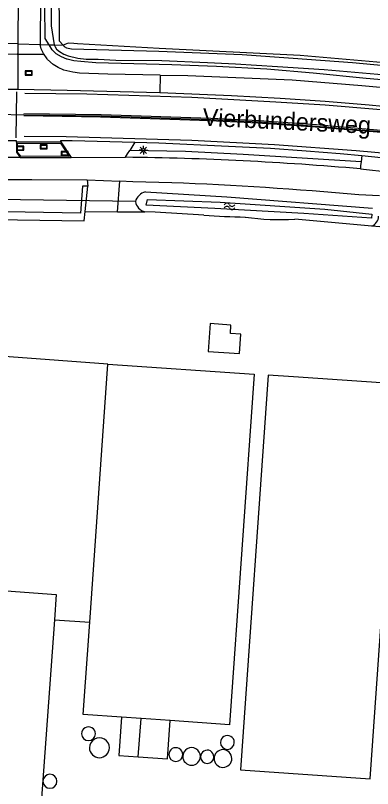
# Model space of a CAD drawing. Extents: x 124000 to 128010, y 398999 to 403000.
# Drawn here: x 125582.7 to 125633.9, y 402700.9 to 402811.8 of the extents above; entities that cross this region are included whole.
import ezdxf

# ---------------------------------------------------------------- set-up
doc = ezdxf.new("R2010")
doc.units = 0
for name, color, linetype in [('gg-afsc-lijn draadraster', 7, 'Continuous'), ('gg-afsc-muur', 7, 'Continuous'), ('gg-anno-openbare ruimte label', 7, 'Continuous'), ('gg-bbg-bijgebouw', 7, 'Continuous'), ('gg-bbg-gedigitaliseerde bijgebouw', 7, 'Continuous'), ('gg-bbg-luifel en loopbrug', 7, 'Continuous'), ('gg-bbg-opslagtank', 7, 'Continuous'), ('gg-bbg-tussenscheiding', 7, 'Continuous'), ('gg-knt-bronhoudergrens', 7, 'Continuous'), ('gg-knt-verharding', 7, 'Continuous'), ('gg-kntw-beschoeiing', 7, 'Continuous'), ('gg-kntw-bovenkant insteek waterloop', 7, 'Continuous'), ('gg-kntw-waterlijn', 7, 'Continuous'), ('gg-kwrk-duiker nz buis', 7, 'Continuous'), ('gt-grn-groengrens', 7, 'Continuous'), ('gt-grn-vlakafsluiter', 7, 'Continuous'), ('gt-grn-weggrens', 7, 'Continuous'), ('gt-symb-bord', 7, 'Continuous'), ('gt-symb-lichtmast', 7, 'Continuous'), ('gt-symb-straatnaambord', 7, 'Continuous'), ('gt-symb-verkeersbord', 7, 'Continuous'), ('gt-symb-watersymbool', 7, 'Continuous'), ('gx-grn-maaiveld', 7, 'Continuous'), ('gx-knt-lijn weginrichtingselement', 7, 'Continuous')]:
    doc.layers.add(name, color=color, linetype=linetype)

# ---------------------------------------------------------------- blocks, each defined once
blk = doc.blocks.new('gt0-BORD')
at = {"layer": 'gt-symb-bord'}
blk.add_lwpolyline([(-0.5, 0.29), (-0.5, -0.29), (0.5, -0.29), (0.5, 0.29), (-0.5, 0.29)], dxfattribs=at)
blk.add_lwpolyline([(-0.42, -0.21), (0.42, -0.21), (0.42, 0.21), (-0.42, 0.21)], close=True, dxfattribs=at)
blk = doc.blocks.new('gt0-LMAST')
at = {"layer": 'gt-symb-lichtmast'}
for p, q in [((-0.18, 0.17), (-0.45, 0.44)), ((-0.01, 0.25), (-0.01, 0.62)), ((0.17, 0.17), (0.44, 0.44)), ((-0.26, 0), (-0.63, 0)), ((-0.18, -0.18), (-0.45, -0.45)), ((-0.01, -0.25), (-0.01, -0.63)), ((0.44, -0.45), (0.17, -0.18)), ((0.24, 0), (0.62, 0))]:
    blk.add_line(p, q, dxfattribs=at)
blk.add_circle((-0.01, 0), 0.25, dxfattribs=at)
blk = doc.blocks.new('gt0-SBORD')
at = {"layer": 'gt-symb-straatnaambord'}
blk.add_lwpolyline([(-0.5, 0.29), (-0.5, -0.29), (0.5, -0.29), (0.5, 0.29), (-0.5, 0.29)], dxfattribs=at)
blk.add_lwpolyline([(-0.42, -0.21), (0.42, -0.21), (0.42, 0.21), (-0.42, 0.21)], close=True, dxfattribs=at)
blk = doc.blocks.new('gt0-VBORD')
at = {"layer": 'gt-symb-verkeersbord'}
blk.add_lwpolyline([(-0.5, 0.29), (-0.5, -0.29), (0.5, -0.29), (0.5, 0.29), (-0.5, 0.29)], dxfattribs=at)
blk.add_lwpolyline([(-0.42, -0.21), (0.42, -0.21), (0.42, 0.21), (-0.42, 0.21)], close=True, dxfattribs=at)
blk = doc.blocks.new('gt0-WA')
at = {"layer": 'gt-symb-watersymbool'}
for centre, start, end in [((-0.32, 0.02), 28.0725, 151.9275), ((0.43, 0.42), 208.0725, 331.9275), ((-0.32, -0.43), 28.0725, 151.9275), ((0.43, -0.03), 208.0725, 331.9275)]:
    blk.add_arc(centre, 0.425, start, end, dxfattribs=at)

msp = doc.modelspace()

# ---------------------------------------------------------------- linework, layer by layer
at = {"layer": 'gg-afsc-lijn draadraster'}
msp.add_lwpolyline([(125692.77, 402796.89), (125673.2, 402800.96), (125670.49, 402801.3), (125660.84, 402802.3), (125646.47, 402803.91), (125635.61, 402805.02), (125623.48, 402806.08), (125603.27, 402807.11), (125591.59, 402807.78), (125591.02, 402807.81), (125590.22, 402807.85)], dxfattribs=at)
at = {"layer": 'gg-afsc-muur'}
msp.add_line((125582.9, 402806.26), (125579.49, 402806.24), dxfattribs=at)
at = {"layer": 'gg-bbg-bijgebouw'}
for p, q in [((125637.43, 402758.95), (125622.53, 402759.98)), ((125600.68, 402710.95), (125597.89, 402711.15)), ((125604.87, 402710.66), (125600.68, 402710.95))]:
    msp.add_line(p, q, dxfattribs=at)
for points in [[(125595.94, 402761.81), (125574.66, 402763.37), (125574.59, 402762.34)], [(125595.94, 402761.81), (125616.89, 402760.36), (125613.35, 402710.06), (125604.87, 402710.66)], [(125622.53, 402759.98), (125618.91, 402760.23), (125614.93, 402703.59)], [(125614.93, 402703.59), (125633.54, 402702.28), (125637.52, 402758.94)], [(125597.89, 402711.15), (125592.4, 402711.54), (125593.33, 402724.76)]]:
    msp.add_lwpolyline(points, dxfattribs=at)
at = {"layer": 'gg-bbg-gedigitaliseerde bijgebouw'}
msp.add_line((125588.27, 402725.13), (125593.33, 402724.76), dxfattribs=at)
msp.add_lwpolyline([(125588.27, 402725.13), (125585.66, 402689), (125581.03, 402689.34)], dxfattribs=at)
at = {"layer": 'gg-bbg-luifel en loopbrug'}
msp.add_line((125600.28, 402705.45), (125600.68, 402710.95), dxfattribs=at)
for points in [[(125610.58, 402767.62), (125610.29, 402763.63), (125614.78, 402763.31), (125614.98, 402766.1), (125613.49, 402766.21), (125613.57, 402767.41), (125610.58, 402767.62)], [(125597.89, 402711.15), (125597.49, 402705.65), (125600.28, 402705.45)], [(125600.28, 402705.45), (125604.47, 402705.15), (125604.87, 402710.66)]]:
    msp.add_lwpolyline(points, dxfattribs=at)
at = {"layer": 'gg-bbg-opslagtank'}
for centre, radius, start, end in [((125593.15, 402708.77), 0.988, 0.0579, 180.116), ((125593.15, 402708.77), 0.988, 180.1159, 0.058), ((125594.71, 402706.76), 1.43, 359.9799, 180.0201), ((125613.06, 402707.52), 0.996, 0.0575, 180.1151), ((125613.06, 402707.52), 0.996, 180.115, 0.0576), ((125594.71, 402706.76), 1.43, 180.0201, 359.9799), ((125605.66, 402705.77), 0.993, 0.0577, 180.1154), ((125607.93, 402705.51), 1.26, 0.0227, 180.0681), ((125610.17, 402705.46), 0.955, 0.0599, 180.12), ((125612.43, 402705.21), 1.27, 0.0903, 180.0451), ((125605.66, 402705.77), 0.993, 180.1154, 0.0577), ((125607.93, 402705.51), 1.26, 180.0681, 0.0227), ((125610.17, 402705.46), 0.955, 180.1199, 0.06), ((125612.43, 402705.21), 1.27, 180.0903, 0.0451), ((125587.62, 402701.94), 1, 0.0856, 180.0856), ((125587.62, 402701.94), 1, 180.0856, 0.0856)]:
    msp.add_arc(centre, radius, start, end, dxfattribs=at)
at = {"layer": 'gg-bbg-tussenscheiding'}
msp.add_line((125593.33, 402724.76), (125595.94, 402761.81), dxfattribs=at)
msp.add_lwpolyline([(125571.65, 402729.97), (125588.53, 402728.75), (125588.27, 402725.13)], dxfattribs=at)
at = {"layer": 'gg-knt-bronhoudergrens'}
for p, q in [((125632.13, 402789.82), (125644.24, 402788.57)), ((125592.96, 402788.24), (125593.07, 402787.35)), ((125592.67, 402783.7), (125593.07, 402787.35))]:
    msp.add_line(p, q, dxfattribs=at)
for points in [[(125593.07, 402787.35), (125592.29, 402787.35), (125592.01, 402783.47), (125557.56, 402784.07), (125557.81, 402787.89)], [(125594.97, 402672.63), (125550.97, 402693.85), (125553.52, 402725.77), (125557.43, 402782.88), (125592.52, 402782.35), (125592.67, 402783.7)]]:
    msp.add_lwpolyline(points, dxfattribs=at)
at = {"layer": 'gg-knt-verharding'}
msp.add_line((125634.88, 402785.97), (125631.93, 402786.09), dxfattribs=at)
msp.add_lwpolyline([(125605.09, 402787.82), (125599.48, 402787.96), (125597.62, 402788.08)], dxfattribs=at)
for centre, radius, start, end in [((125593.63, 402353.4), 438.11, 84.9589, 89.3681), ((125584.76, 402263.53), 524.69, 84.8429, 87.7796)]:
    msp.add_arc(centre, radius, start, end, dxfattribs=at)
at = {"layer": 'gg-kntw-beschoeiing'}
msp.add_line((125582.9, 402806.26), (125586.7, 402806.27), dxfattribs=at)
at = {"layer": 'gg-kntw-bovenkant insteek waterloop'}
for p, q in [((125602.71, 402783.59), (125601.22, 402783.67)), ((125609.69, 402783.19), (125602.71, 402783.59)), ((125633.76, 402781.59), (125622.73, 402782.59))]:
    msp.add_line(p, q, dxfattribs=at)
msp.add_lwpolyline([(125601.3, 402786.51), (125612.99, 402785.81), (125633.87, 402784.18)], dxfattribs=at)
for centre, radius, start, end in [((125601.67, 402784.69), 1.85, 101.5261, 166.2673), ((125601.61, 402785.39), 1.76, 188.3735, 257.1885), ((125618.54, 402902), 119.14, 265.7375, 268.6002), ((125620.8, 402819.57), 37.03, 261.9878, 272.9917), ((125633.08, 402783.1), 1.67, 294.3526, 357.2073)]:
    msp.add_arc(centre, radius, start, end, dxfattribs=at)
at = {"layer": 'gg-kntw-waterlijn'}
msp.add_lwpolyline([(125601.61, 402785.43), (125612.04, 402785.05), (125627.01, 402784.04), (125633.79, 402783.34), (125633.73, 402782.73), (125624.04, 402783.4), (125611.27, 402784.15), (125601.4, 402784.59), (125601.61, 402785.43)], dxfattribs=at)
at = {"layer": 'gg-kwrk-duiker nz buis'}
msp.add_line((125599.87, 402785.13), (125546.26, 402785.98), dxfattribs=at)
at = {"layer": 'gt-grn-groengrens'}
for p, q in [((125597.29, 402783.64), (125601.22, 402783.67)), ((125635.51, 402781.44), (125633.76, 402781.59))]:
    msp.add_line(p, q, dxfattribs=at)
at = {"layer": 'gt-grn-vlakafsluiter'}
msp.add_line((125597.29, 402783.64), (125597.62, 402788.08), dxfattribs=at)
at = {"layer": 'gt-grn-weggrens'}
msp.add_line((125592.67, 402783.7), (125597.29, 402783.64), dxfattribs=at)
at = {"layer": 'gx-grn-maaiveld'}
for p, q in [((125583.13, 402819.31), (125583, 402807.76)), ((125586.3, 402819.29), (125586.2, 402807.66)), ((125583, 402807.76), (125577.64, 402807.87)), ((125583, 402807.76), (125583.03, 402805.68)), ((125583, 402807.76), (125586.2, 402807.66)), ((125586.2, 402807.66), (125587.51, 402807.63)), ((125587.51, 402807.63), (125588.23, 402807.61)), ((125588.23, 402807.61), (125589.51, 402807.57)), ((125583.03, 402805.68), (125583.01, 402801.27)), ((125603.41, 402803.28), (125603.38, 402800.8)), ((125581.3, 402801.26), (125583.01, 402801.27)), ((125589.19, 402793.68), (125582.81, 402793.67)), ((125589.19, 402793.68), (125590.64, 402791.43)), ((125599.79, 402793.65), (125599.07, 402792.48)), ((125583.37, 402791.47), (125580.84, 402791.46)), ((125583.37, 402791.47), (125590.64, 402791.43)), ((125590.64, 402791.43), (125598.46, 402791.49)), ((125632.35, 402791.75), (125632.22, 402790.82)), ((125632.35, 402791.75), (125644.49, 402790.5)), ((125592.96, 402788.24), (125597.62, 402788.08))]:
    msp.add_line(p, q, dxfattribs=at)
for points in [[(125624.11, 402880.43), (125606.85, 402854.76), (125588.86, 402825.8), (125588.93, 402808.19), (125589.51, 402807.57)], [(125587.84, 402820.39), (125587.79, 402810.33), (125588.23, 402807.61)], [(125587.51, 402807.63), (125586.93, 402808.55), (125586.9, 402813.2)], [(125587.2, 402805.63), (125586.67, 402806.4), (125586.38, 402807.06), (125586.2, 402807.66)], [(125590.03, 402805.58), (125589.26, 402805.89), (125588.53, 402806.35), (125587.95, 402806.92), (125587.51, 402807.63)], [(125588.23, 402807.61), (125588.36, 402807.35), (125588.57, 402807.02), (125589.01, 402806.64), (125589.6, 402806.3), (125590.24, 402806.06), (125591.64, 402805.72), (125592.79, 402805.57), (125594.51, 402805.55), (125597.06, 402805.42), (125603.66, 402805.37), (125610.22, 402805.09), (125614.2, 402804.89), (125620.25, 402804.52), (125626.95, 402804.06), (125635.71, 402803.3), (125643, 402802.53), (125643.44, 402802.45)], [(125692.77, 402796.89), (125673.2, 402800.96), (125670.49, 402801.3), (125660.84, 402802.3), (125646.47, 402803.91), (125635.61, 402805.02), (125623.48, 402806.08), (125603.27, 402807.11), (125591.59, 402807.78), (125591.02, 402807.81), (125590.22, 402807.85), (125589.51, 402807.57)], [(125589.51, 402807.57), (125589.64, 402807.38), (125589.98, 402807.19), (125590.7, 402807.04), (125603.21, 402806.71), (125615.19, 402806.21), (125622.48, 402805.72), (125630.99, 402805.1), (125644.75, 402803.79), (125645.29, 402803.24), (125645.32, 402802.47), (125645.27, 402802.25)], [(125603.41, 402803.28), (125595.9, 402803.39), (125591.85, 402803.57), (125590.88, 402803.7), (125590.02, 402803.87), (125589.62, 402803.99), (125588.82, 402804.35), (125588.07, 402804.81), (125587.28, 402805.51), (125587.2, 402805.63)], [(125643.44, 402802.45), (125643.75, 402802.31), (125643.84, 402802.09), (125643.73, 402801.83), (125643.22, 402801.8), (125640.75, 402802.11), (125632.98, 402802.79), (125625.37, 402803.56), (125618.7, 402804.13), (125611.48, 402804.51), (125605.09, 402804.74), (125594.2, 402805.06), (125592.03, 402805.21), (125591.02, 402805.32), (125590.09, 402805.56), (125590.03, 402805.58)], [(125503.37, 402802.49), (125503.37, 402802.49), (125503.48, 402802.47), (125515, 402800.95), (125523.4, 402799.99), (125534.14, 402799.07), (125543.3, 402798.51), (125553.95, 402798.05), (125565.15, 402797.74), (125573.95, 402797.68), (125580.13, 402797.65), (125583.86, 402797.57), (125594.95, 402797.42), (125610.7, 402796.9), (125617.61, 402796.58), (125625.81, 402795.97), (125634.54, 402795.24), (125643.89, 402794.37), (125646.28, 402794.06)], [(125603.41, 402803.28), (125607.4, 402803.22), (125622.36, 402802.62), (125632.36, 402801.78), (125638.7, 402801.21), (125643.78, 402800.61), (125644.21, 402800.77), (125644.53, 402800.98), (125644.99, 402801.34), (125645.18, 402801.84), (125645.27, 402802.25)], [(125583.01, 402801.27), (125590.09, 402801.12), (125603.38, 402800.8)], [(125603.38, 402800.8), (125613.65, 402800.37), (125620.61, 402799.97), (125627.1, 402799.52), (125633.38, 402798.99), (125639.26, 402798.42), (125645.32, 402797.78), (125646.7, 402797.63)], [(125582.81, 402793.67), (125582.81, 402793.86), (125581.29, 402793.86), (125581.3, 402793.65)], [(125582.81, 402793.67), (125582.8, 402792.2), (125583.37, 402791.47)], [(125589.19, 402793.68), (125589.2, 402793.89), (125590.82, 402793.87), (125599.79, 402793.65)], [(125599.79, 402793.65), (125603.25, 402793.57), (125613.22, 402793.1), (125619.26, 402792.78), (125624.35, 402792.41), (125629.25, 402792.02), (125632.35, 402791.75)], [(125583.44, 402791.63), (125582.95, 402792.22), (125582.98, 402793.52), (125589.11, 402793.53), (125590.37, 402791.6), (125583.44, 402791.63)], [(125598.46, 402791.49), (125598.76, 402791.98), (125599.07, 402792.48)], [(125632.22, 402790.82), (125615.34, 402791.88), (125607.06, 402792.32), (125599.07, 402792.48)], [(125632.22, 402790.82), (125632.15, 402790.3), (125632.13, 402789.82)], [(125557.85, 402788.72), (125560.11, 402788.62), (125563.5, 402788.53), (125568.08, 402788.4), (125578.24, 402788.29), (125585.04, 402788.31), (125592.96, 402788.24)]]:
    msp.add_lwpolyline(points, dxfattribs=at)
at = {"layer": 'gx-knt-lijn weginrichtingselement'}
msp.add_line((125582.77, 402794.29), (125582.87, 402800.88), dxfattribs=at)
for points in [[(125584.02, 402800.69), (125592.93, 402800.58), (125607.95, 402800.1), (125620.01, 402799.45), (125627.09, 402799), (125634.47, 402798.38), (125639.89, 402797.88), (125645.71, 402797.26), (125646.64, 402797.14), (125650.01, 402796.72), (125658.88, 402795.43), (125667.94, 402794.01), (125675.82, 402792.69), (125681.43, 402791.61), (125690.03, 402789.86), (125697.11, 402788.36), (125705.93, 402786.26)], [(125583.86, 402797.77), (125594.96, 402797.62), (125610.7, 402797.09), (125617.62, 402796.78), (125625.82, 402796.17), (125634.56, 402795.44), (125643.91, 402794.57), (125646.3, 402794.26), (125649.42, 402793.86), (125658.33, 402792.62), (125666.16, 402791.36), (125673.8, 402790.05), (125684.84, 402787.98), (125696.54, 402785.46), (125704.97, 402783.47), (125711.89, 402781.77)], [(125711.53, 402781.5), (125704.28, 402783.32), (125696.46, 402785.1), (125684.75, 402787.6), (125673.73, 402789.72), (125665.76, 402791.09), (125657.06, 402792.46), (125649.49, 402793.5), (125646.26, 402793.89), (125643.71, 402794.2), (125634.55, 402795.08), (125625.7, 402795.82), (125617.44, 402796.36), (125610.48, 402796.7), (125594.86, 402797.26), (125583.89, 402797.41)], [(125787.96, 402751.7), (125776.76, 402756.56), (125765.53, 402761.04), (125756.22, 402764.54), (125744.02, 402768.78), (125742.51, 402769.26), (125728.15, 402773.82), (125714.61, 402777.71), (125699.15, 402781.51), (125679.92, 402785.55), (125667.09, 402787.88), (125649.45, 402790.53), (125646.2, 402790.97), (125640.64, 402791.58), (125631.54, 402792.4), (125619.81, 402793.25), (125607.95, 402793.91), (125589.96, 402794.42), (125583.91, 402794.48)]]:
    msp.add_lwpolyline(points, dxfattribs=at)

# ---------------------------------------------------------------- block references
at = {"layer": 'gt-symb-bord'}
for p in [(125583.36, 402792.78), (125586.73, 402792.98), (125589.74, 402792.03)]:
    msp.add_blockref('gt0-BORD', p, dxfattribs=at)
at = {"layer": 'gt-symb-lichtmast'}
msp.add_blockref('gt0-LMAST', (125601.02, 402792.49), dxfattribs=at)
at = {"layer": 'gt-symb-straatnaambord'}
msp.add_blockref('gt0-SBORD', (125584.58, 402803.58), dxfattribs=at)
at = {"layer": 'gt-symb-verkeersbord'}
msp.add_blockref('gt0-VBORD', (125584.58, 402803.58), dxfattribs=at)
at = {"layer": 'gt-symb-watersymbool'}
msp.add_blockref('gt0-WA', (125613.31, 402784.45), dxfattribs=at)

# ---------------------------------------------------------------- texts
at = {"layer": 'gg-anno-openbare ruimte label'}
msp.add_text('Vierbundersweg', height=2.5, rotation=357.2, dxfattribs=at).set_placement((125609.46, 402796.02))

doc.saveas('drawing.dxf')
